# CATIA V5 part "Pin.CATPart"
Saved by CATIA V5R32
Part number: Pin
Bounding box of the stored display mesh (mm): x -15 to 15, y -15 to 15, z -50 to 0
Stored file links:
  D:\PROJECTS\Project 2022\CATIA V5 6R 2022\Resources\Part Files\c12_catia_v5_6r2022_prt\c12_catia_v5-6r2022 figr_12-30\Pin.CATPart
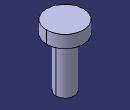
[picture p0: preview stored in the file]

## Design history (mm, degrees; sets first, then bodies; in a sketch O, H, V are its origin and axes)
Body1 (main body)
  Sketch1 on xy-plane, origin (0, 0, 0), H (1, 0, 0), V (0, 1, 0)
    circle A1 centre (0, 0) radius 15
    circle A2 centre (0, 0) radius 7.5
    radius A2 = 7.5
    radius A1 = 15
  MultiPad1: profile Sketch1, domains (length -50; length -10)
